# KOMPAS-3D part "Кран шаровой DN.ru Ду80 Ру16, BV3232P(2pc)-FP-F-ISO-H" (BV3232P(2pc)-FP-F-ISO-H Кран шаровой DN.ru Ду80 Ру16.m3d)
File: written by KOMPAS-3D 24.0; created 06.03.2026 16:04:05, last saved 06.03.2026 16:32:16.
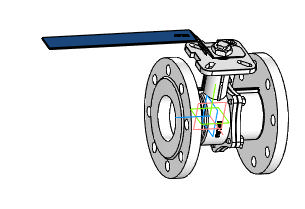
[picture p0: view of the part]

Document properties: Автор: R2D2; Полное имя файла: E:\Работа\Зайцев\BV3232P(2pc)-FP-F-ISO-H Кран шаровой DN.ru Ду15-300 Ру16-40\DN80 PN16\BV3232P(2pc)-FP-F-ISO-H Кран шаровой DN.ru Ду80 Ру16.m3d

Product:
- Part/product: Кран шаровой DN.ru Ду80 Ру16  | designation BV3232P(2pc)-FP-F-ISO-H
    Масса: 12.93
    Раздел спецификации: Прочие изделия
    Примечание: D160-22136

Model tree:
1. Операция без истории:1

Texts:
  BV3232P(2pc)-FP-F-ISO-H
